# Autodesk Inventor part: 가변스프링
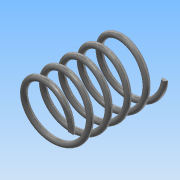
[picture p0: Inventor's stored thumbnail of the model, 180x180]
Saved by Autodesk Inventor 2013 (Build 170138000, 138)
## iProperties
Created: 2017-01
Part Number: 가변스프링
Material: 스테인리스강
Document SubType Name: Modeling
Designer: Administrator
Mass: 63.157 g
Surface Area: 79.1135 cm^2
Volume: 7.81647 cm^3
Density: 8.08 g/cm^3
Author: Administrator
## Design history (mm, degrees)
sketch "스케치1"
  geometry: L1 (0, 0)-(20, 0); L2 (20, 0)-(20, 67.25); L3 (20, 67.25)-(0, 67.25); L4 (0, 67.25)-(0, 0); C1 r 2 at (20, 0)
  constraints: 8 end point, 2 parallel, 1 centre point, 1 coincident, 1 horizontal, 1 perpendicular
  dimensions: "d0" = 4 diameter of C1; "d2" = 67.25 distance of L3.end L1.start (derived); "d3" = 40 diameter of L2 L4
feature "코일1" sketch "스케치1" pitch "d4" = 10; turns "d6" = 5; dims "d5" = 67.25 (= d2), "d7" = 0, angle "d8" = 90 deg, angle "d9" = 90 deg, "d10" = 0, "d11" = 0
sketch "스케치2"
  geometry: L1 (0, 26.801)-(67.25, 26.801); L2 (67.25, 26.801)-(67.25, -26.801); L3 (67.25, -26.801)-(0, -26.801); L4 (0, -26.801)-(0, 26.801); 4 further points
  constraints: 8 end point, 2 coincident, 2 midpoint, 2 parallel, 1 horizontal, 1 perpendicular
  dimensions: "d12" = 53.60174 distance of L1.end L2.end
extrude "돌출1" sketch "스케치2" stored distance "d14" = 0; taper "d15" = 0 deg
node "솔리드1"
